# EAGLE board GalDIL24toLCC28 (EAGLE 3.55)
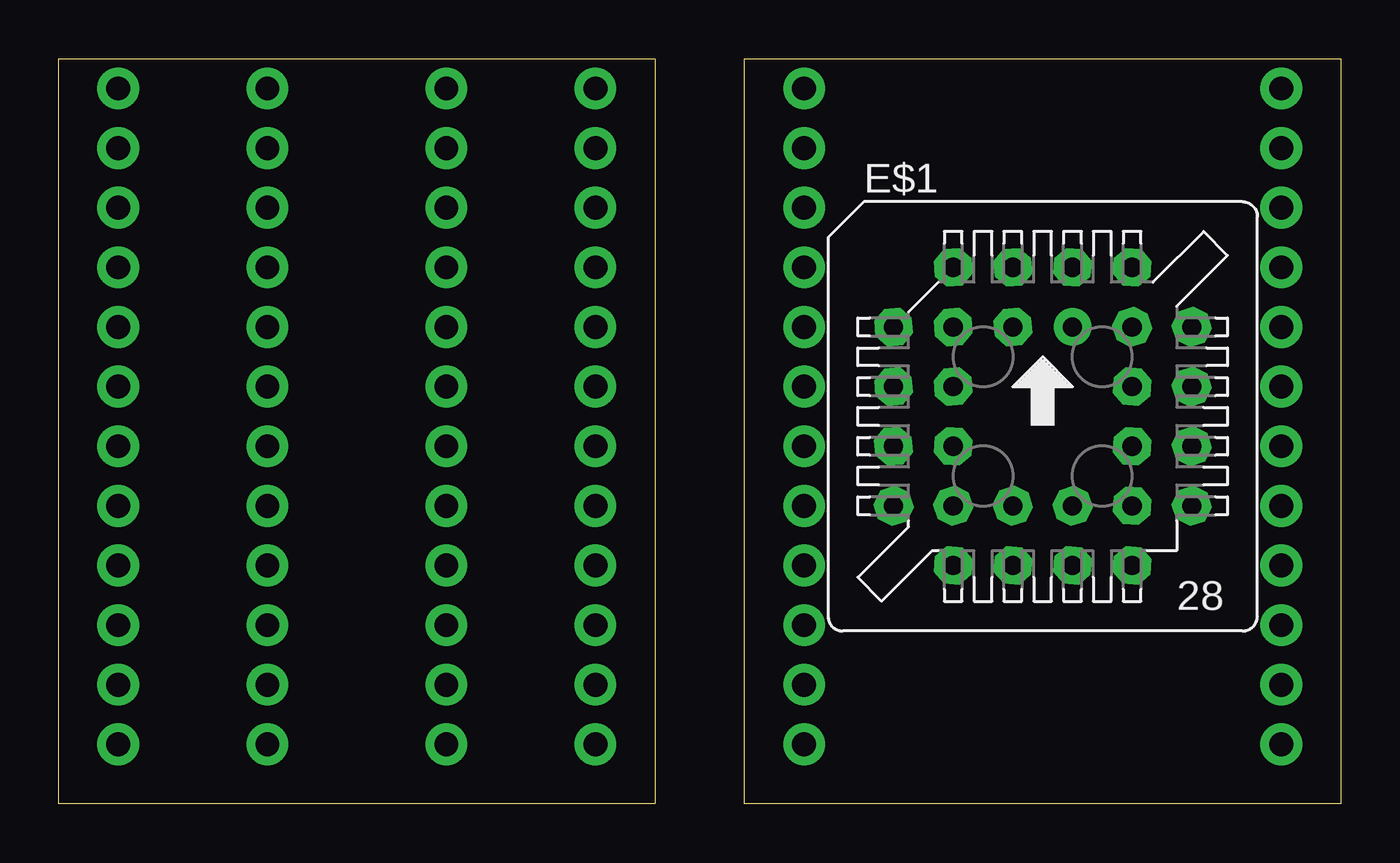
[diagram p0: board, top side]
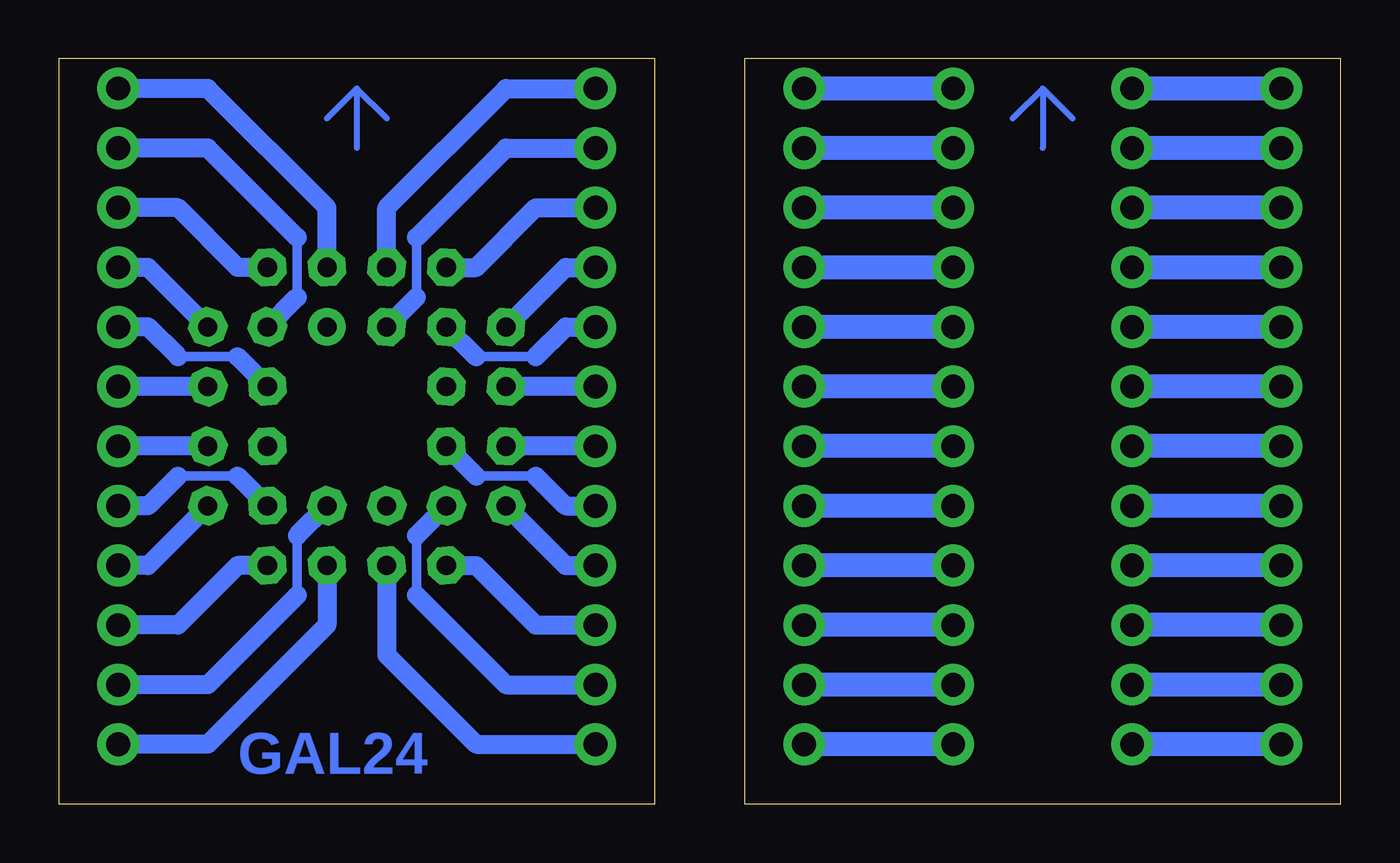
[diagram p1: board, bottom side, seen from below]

Size 54.61 x 31.75 mm. Coordinates in mm from the lower left corner, seen from the top.
Outline: 25.4,31.75 25.4,0 0,0 0,31.75 25.4,31.75
Outline: 29.21,31.75 54.61,31.75 54.61,0 29.21,0 29.21,31.75
Copper layers used: Bottom

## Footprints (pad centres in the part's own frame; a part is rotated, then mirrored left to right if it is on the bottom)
8 = drill 0.813 pad 1.6 round:  1.27,3.81 | drill 0.813 pad 1.6 octagon:  -1.27,6.35;  -1.27,3.81;  -3.81,6.35;  -6.35,3.81;  -3.81,3.81;  -6.35,1.27;  -3.81,1.27;  -6.35,-1.27;  -3.81,-1.27;  -6.35,-3.81;  -3.81,-6.35;  -3.81,-3.81;  -1.27,-6.35;  -1.27,-3.81;  1.27,-6.35;  1.27,-3.81;  3.81,-6.35;  6.35,-3.81;  3.81,-3.81;  6.35,-1.27;  3.81,-1.27;  6.35,1.27;  3.81,1.27;  6.35,3.81;  3.81,6.35;  3.81,3.81;  1.27,6.35
AD10 = drill 1.016 pad 1.778 round:  0,0

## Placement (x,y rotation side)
E$1  [8]  41.91,16.51 0 top
E$7  [AD10]  2.54,30.48 0 top
E$8  [AD10]  2.54,27.94 0 top
E$9  [AD10]  2.54,25.4 0 top
E$10  [AD10]  2.54,22.86 0 top
E$11  [AD10]  2.54,20.32 0 top
E$12  [AD10]  2.54,17.78 0 top
E$13  [AD10]  2.54,15.24 0 top
E$14  [AD10]  2.54,12.7 0 top
E$15  [AD10]  2.54,10.16 0 top
E$16  [AD10]  2.54,7.62 0 top
E$17  [AD10]  2.54,5.08 0 top
E$18  [AD10]  2.54,2.54 0 top
E$23  [AD10]  22.86,30.48 0 top
E$24  [AD10]  22.86,27.94 0 top
E$25  [AD10]  22.86,25.4 0 top
E$26  [AD10]  22.86,22.86 0 top
E$27  [AD10]  22.86,20.32 0 top
E$28  [AD10]  22.86,17.78 0 top
E$29  [AD10]  22.86,15.24 0 top
E$30  [AD10]  22.86,12.7 0 top
E$31  [AD10]  22.86,10.16 0 top
E$32  [AD10]  22.86,7.62 0 top
E$33  [AD10]  22.86,5.08 0 top
E$34  [AD10]  22.86,2.54 0 top
E$39  [AD10]  8.89,30.48 0 top
E$40  [AD10]  8.89,27.94 0 top
E$41  [AD10]  8.89,25.4 0 top
E$42  [AD10]  8.89,22.86 0 top
E$43  [AD10]  8.89,20.32 0 top
E$44  [AD10]  8.89,17.78 0 top
E$45  [AD10]  8.89,15.24 0 top
E$46  [AD10]  8.89,12.7 0 top
E$47  [AD10]  8.89,10.16 0 top
E$48  [AD10]  8.89,7.62 0 top
E$49  [AD10]  8.89,5.08 0 top
E$50  [AD10]  8.89,2.54 0 top
E$55  [AD10]  16.51,30.48 0 top
E$56  [AD10]  16.51,27.94 0 top
E$57  [AD10]  16.51,25.4 0 top
E$58  [AD10]  16.51,22.86 0 top
E$59  [AD10]  16.51,20.32 0 top
E$60  [AD10]  16.51,17.78 0 top
E$61  [AD10]  16.51,15.24 0 top
E$62  [AD10]  16.51,12.7 0 top
E$63  [AD10]  16.51,10.16 0 top
E$64  [AD10]  16.51,7.62 0 top
E$65  [AD10]  16.51,5.08 0 top
E$66  [AD10]  16.51,2.54 0 top
E$70  [AD10]  31.75,30.48 0 top
E$71  [AD10]  31.75,27.94 0 top
E$72  [AD10]  31.75,25.4 0 top
E$73  [AD10]  31.75,22.86 0 top
E$74  [AD10]  31.75,20.32 0 top
E$75  [AD10]  31.75,17.78 0 top
E$76  [AD10]  31.75,15.24 0 top
E$77  [AD10]  31.75,12.7 0 top
E$78  [AD10]  31.75,10.16 0 top
E$79  [AD10]  31.75,7.62 0 top
E$80  [AD10]  31.75,5.08 0 top
E$81  [AD10]  31.75,2.54 0 top
E$86  [AD10]  52.07,30.48 0 top
E$87  [AD10]  52.07,27.94 0 top
E$88  [AD10]  52.07,25.4 0 top
E$89  [AD10]  52.07,22.86 0 top
E$90  [AD10]  52.07,20.32 0 top
E$91  [AD10]  52.07,17.78 0 top
E$92  [AD10]  52.07,15.24 0 top
E$93  [AD10]  52.07,12.7 0 top
E$94  [AD10]  52.07,10.16 0 top
E$95  [AD10]  52.07,7.62 0 top
E$96  [AD10]  52.07,5.08 0 top
E$97  [AD10]  52.07,2.54 0 top

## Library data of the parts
E$1 = PLCCPACK
E$7-E$18 E$23-E$34 E$39-E$50 E$55-E$66 E$70-E$81 E$86-E$97 = holgnorm

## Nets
S$1: E$1. E$70.
S$2: E$1. E$71.
S$3: E$1. E$72.
S$4: E$1. E$73.
S$5: E$7. E$39.
S$6: E$8. E$40.
S$7: E$9. E$41.
S$8: E$10. E$42.
S$9: E$11. E$43.
S$10: E$12. E$44.
S$11: E$13. E$45.
S$12: E$14. E$46.
S$13: E$15. E$47.
S$14: E$16. E$48.
S$15: E$17. E$49.
S$16: E$18. E$50.
S$17: E$1. E$74.
S$18: E$1. E$75.
S$19: E$1. E$76.
S$20: E$1. E$77.
S$21: E$23. E$55.
S$22: E$24. E$56.
S$23: E$25. E$57.
S$24: E$26. E$58.
S$25: E$27. E$59.
S$26: E$28. E$60.
S$27: E$29. E$61.
S$28: E$30. E$62.
S$29: E$31. E$63.
S$30: E$32. E$64.
S$31: E$33. E$65.
S$32: E$34. E$66.
S$33: E$1. E$78.
S$34: E$1. E$79.
S$35: E$1. E$80.
S$36: E$1. E$81.
S$37: E$1. E$97.
S$38: E$1. E$96.
S$39: E$1. E$95.
S$40: E$1. E$94.
S$41: E$1. E$93.
S$42: E$1. E$92.
S$43: E$1. E$91.
S$44: E$1. E$90.
S$45: E$1. E$89.
S$46: E$1. E$88.
S$47: E$1. E$87.
S$48: E$1. E$86.

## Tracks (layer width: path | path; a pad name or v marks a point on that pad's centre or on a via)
S$1
  Bottom 0.813: 40.64,22.86 40.64,25.4 35.56,30.48 E$70.
S$2
  Bottom 0.406: 39.37,21.59 39.37,24.13
  Bottom 0.813: 40.64,20.32 39.37,21.59 | 39.37,24.13 35.56,27.94 E$71.
S$3
  Bottom 0.813: 38.1,22.86 36.83,22.86 34.29,25.4 E$72.
S$4
  Bottom 0.813: 35.56,20.32 33.02,22.86 E$73.
S$5
  Bottom 1.016: E$7. E$39.
S$6
  Bottom 1.016: E$8. E$40.
S$7
  Bottom 1.016: E$9. E$41.
S$8
  Bottom 1.016: E$10. E$42.
S$9
  Bottom 1.016: E$11. E$43.
S$10
  Bottom 1.016: E$12. E$44.
S$11
  Bottom 1.016: E$13. E$45.
S$12
  Bottom 1.016: E$14. E$46.
S$13
  Bottom 1.016: E$15. E$47.
S$14
  Bottom 1.016: E$16. E$48.
S$15
  Bottom 1.016: E$17. E$49.
S$16
  Bottom 1.016: E$18. E$50.
S$17
  Bottom 0.406: 36.83,19.05 34.29,19.05
  Bottom 0.813: 38.1,20.32 36.83,19.05 | 34.29,19.05 33.02,20.32 E$74.
S$18
  Bottom 0.813: E$75. 35.56,17.78
S$19
  Bottom 0.813: E$76. 35.56,15.24
S$20
  Bottom 0.406: 36.83,13.97 34.29,13.97
  Bottom 0.813: 38.1,15.24 36.83,13.97 | 34.29,13.97 33.02,12.7 E$77.
S$21
  Bottom 1.016: E$55. E$23.
S$22
  Bottom 1.016: E$56. E$24.
S$23
  Bottom 1.016: E$57. E$25.
S$24
  Bottom 1.016: E$58. E$26.
S$25
  Bottom 1.016: E$59. E$27.
S$26
  Bottom 1.016: E$60. E$28.
S$27
  Bottom 1.016: E$61. E$29.
S$28
  Bottom 1.016: E$62. E$30.
S$29
  Bottom 1.016: E$63. E$31.
S$30
  Bottom 1.016: E$64. E$32.
S$31
  Bottom 1.016: E$65. E$33.
S$32
  Bottom 1.016: E$66. E$34.
S$33
  Bottom 0.813: 35.56,12.7 33.02,10.16 E$78.
S$34
  Bottom 0.813: 38.1,10.16 36.83,10.16 34.29,7.62 E$79.
S$35
  Bottom 0.406: 39.37,11.43 39.37,8.89
  Bottom 0.813: 38.1,12.7 39.37,11.43 | 39.37,8.89 35.56,5.08 E$80.
S$36
  Bottom 0.813: 40.64,10.16 40.64,6.35 36.83,2.54 E$81.
S$37
  Bottom 0.813: 43.18,10.16 43.18,7.62 48.26,2.54 E$97.
S$38
  Bottom 0.406: 44.45,11.43 44.45,8.89
  Bottom 0.813: 43.18,12.7 44.45,11.43 | 44.45,8.89 48.26,5.08 E$96.
S$39
  Bottom 0.813: 45.72,10.16 46.99,10.16 49.53,7.62 E$95.
S$40
  Bottom 0.813: 48.26,12.7 50.8,10.16 E$94.
S$41
  Bottom 0.406: 46.99,13.97 49.53,13.97
  Bottom 0.813: 45.72,12.7 46.99,13.97 | 49.53,13.97 50.8,12.7 E$93.
S$42
  Bottom 0.813: 48.26,15.24 E$92.
S$43
  Bottom 0.813: 48.26,17.78 E$91.
S$44
  Bottom 0.406: 46.99,19.05 49.53,19.05
  Bottom 0.813: 45.72,17.78 46.99,19.05 | 49.53,19.05 50.8,20.32 E$90.
S$45
  Bottom 0.813: 48.26,20.32 50.8,22.86 E$89.
S$46
  Bottom 0.813: 45.72,22.86 46.99,22.86 49.53,25.4 E$88.
S$47
  Bottom 0.406: 44.45,21.59 44.45,24.13
  Bottom 0.813: 45.72,20.32 44.45,21.59 | 44.45,24.13 48.26,27.94 E$87.
S$48
  Bottom 0.813: E$1. 43.18,25.4 48.26,30.48 E$86.
S$65
  Bottom 0.254: 41.91,30.48 41.91,27.94 | 40.64,29.21 41.91,30.48 | 41.91,30.48 43.18,29.21 | 12.7,30.48 12.7,27.94
S$66
  Bottom 0.254: 11.43,29.21 12.7,30.48 13.97,29.21

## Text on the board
Bottom: GAL24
